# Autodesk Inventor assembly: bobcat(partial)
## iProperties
Author: vincent molino
Shininess: 64.0
Angle Display Precision: 2
Document Length Units: 11272
Document Angle Units: 11286
Document Time Units: 11279
Document Mass Units: 11290
Document Length Units Precision: 3
Document Angle Units Precision: 2
Compacted: True
PropertySet Name: _Private Model Information
Created: 2002-01
Part Number: bobcat(partial)
Document SubType Name: Assembly
Designer: vincent molino
Control State: 0
Master: False
Checked Out: False
PropertySet Name: Design Tracking Control
Density: 0.0
Volumn: 0.0
Area: 0.0
PropertySet Name: Model Information
